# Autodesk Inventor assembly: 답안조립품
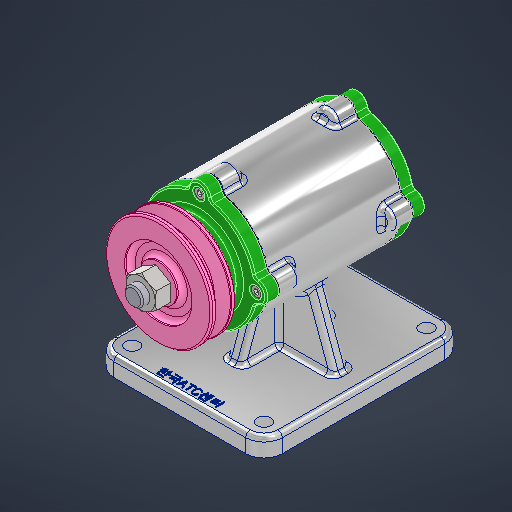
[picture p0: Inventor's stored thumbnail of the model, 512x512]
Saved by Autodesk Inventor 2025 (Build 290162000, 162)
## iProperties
Created: 2025-08
Part Number: 답안조립품
Document SubType Name: Assembly
Designer: infra027
Author: infra027
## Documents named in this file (12)
- C:\Users\infra027\Desktop\750806V1003\답안조립품.iam
- C:\Users\infra027\Desktop\750806V1003\본체.ipt
- C:\Users\infra027\Desktop\20195166\공용부품_20250517_2\V-벨트풀리\V-벨트풀리.ipt
- C:\Users\infra027\Desktop\20195166\공용부품_20250517_2\개스킷\개스킷.ipt
- C:\Users\infra027\Desktop\20195166\공용부품_20250517_2\너트 M12 x 1.25\너트 M12 x 1.25.ipt
- C:\Users\infra027\Desktop\20195166\공용부품_20250517_2\뒤커버\뒤커버.ipt
- C:\Users\infra027\Desktop\20195166\공용부품_20250517_2\베어링 6204\베어링 6204.ipt
- C:\Users\infra027\Desktop\20195166\공용부품_20250517_2\볼트 M4 x 12\볼트 M4 x 12.ipt
- C:\Users\infra027\Desktop\20195166\공용부품_20250517_2\앞커버\앞커버.ipt
- C:\Users\infra027\Desktop\20195166\공용부품_20250517_2\오일 실\오일 실.ipt
- C:\Users\infra027\Desktop\20195166\공용부품_20250517_2\축\축.ipt
- C:\Users\infra027\Desktop\20195166\공용부품_20250517_2\키 4 x 4\키 4 x 4.ipt
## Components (3 placed, 2 different names)
1. V-벨트풀리:1
2. 개스킷:1
3. 개스킷:2
